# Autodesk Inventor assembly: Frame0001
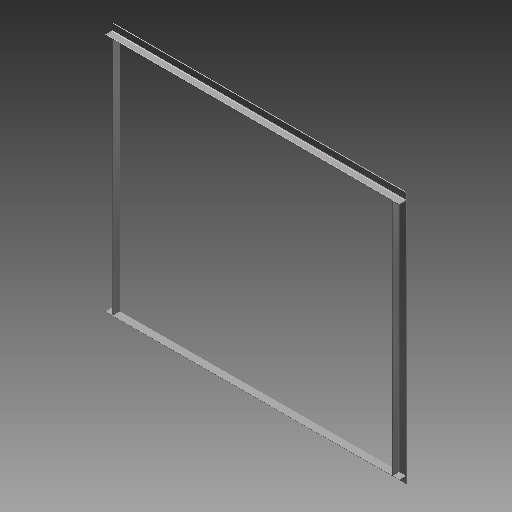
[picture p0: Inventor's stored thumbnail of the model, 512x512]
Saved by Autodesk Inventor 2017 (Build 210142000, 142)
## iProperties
Created: 2020-09
Part Number: Frame0001
Document SubType Name: Assembly
Designer: X
_FrameDoc: Frame Assembly
_Version: 15.0.0
Author: X
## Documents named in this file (10)
- C:\Users\X\Desktop\brama\rama_bramy\Frame\Frame0001.iam
- C:\Users\X\Desktop\brama\rama_bramy\Frame\Skeleton0001.ipt
- C:\Users\X\Desktop\brama\rama_bramy\Frame\PN L60x60x5 00000005.ipt
- PN L60x60x5 00000005.ipt
- C:\Users\X\Desktop\brama\rama_bramy\Frame\PN L60x60x5 00000006.ipt
- PN L60x60x5 00000006.ipt
- C:\Users\X\Desktop\brama\rama_bramy\Frame\PN L60x60x5 00000007.ipt
- PN L60x60x5 00000007.ipt
- C:\Users\X\Desktop\brama\rama_bramy\Frame\PN L60x60x5 00000008.ipt
- PN L60x60x5 00000008.ipt
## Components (5 placed, 5 different names)
1. Model odniesienia ramy
2. PN L60x60x5 00000005:1
3. PN L60x60x5 00000006:1
4. PN L60x60x5 00000007:1
5. PN L60x60x5 00000008:1
